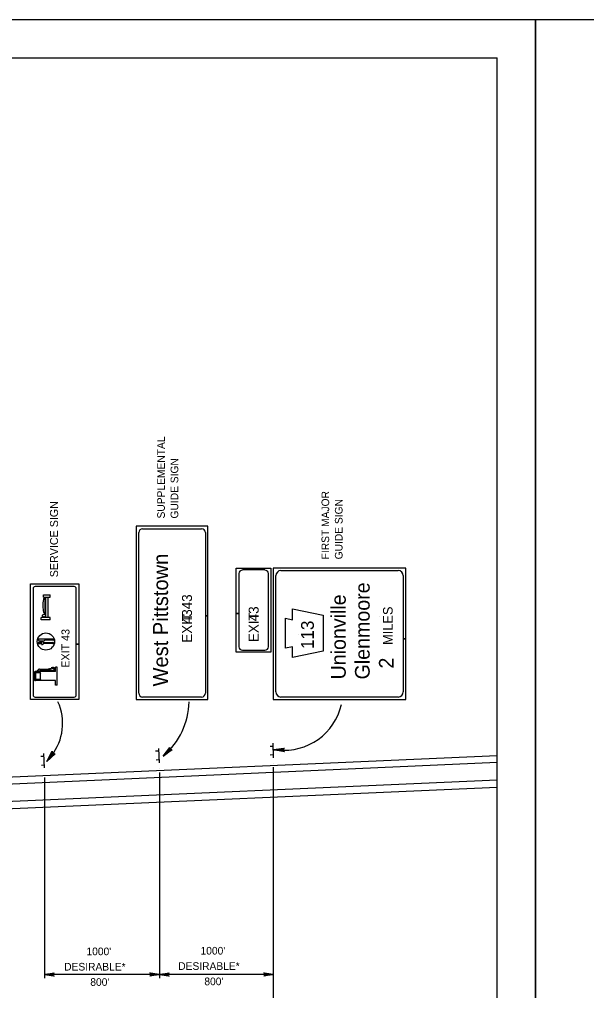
# Model space of a CAD drawing. Extents: x 644898 to 648326, y 298294 to 300670.
# Drawn here: x 646378.1 to 646600.3, y 300290.3 to 300670.5 of the extents above; entities that cross this region are included whole.
import ezdxf

# ---------------------------------------------------------------- set-up
doc = ezdxf.new("R2010")
doc.units = 0
for name, color, linetype in [('1', 7, 'Continuous'), ('2', 7, 'Continuous'), ('XCS-GRID-MIN', 7, 'Continuous')]:
    doc.layers.add(name, color=color, linetype=linetype)

msp = doc.modelspace()

# ---------------------------------------------------------------- linework, layer by layer
at = {"layer": '1'}
for p in [(645779.32, 300655.49), (646565.32, 300091.49)]:
    msp.add_line(p, (646565.32, 300655.49), dxfattribs=at)
at = {"layer": '2'}
for p, q in [((646451.95, 300472.12), (646423.82, 300472.12)), ((646423.82, 300472.12), (646423.82, 300404.24)), ((646424.82, 300406.74), (646424.82, 300469.62)), ((646426.32, 300471.12), (646426.32, 300471.12)), ((646426.32, 300471.12), (646449.45, 300471.12)), ((646449.45, 300471.12), (646449.45, 300471.12)), ((646450.95, 300469.62), (646450.95, 300436.98)), ((646451.95, 300436.98), (646451.95, 300472.12)), ((646463.07, 300437.92), (646463.07, 300455.74)), ((646463.07, 300455.74), (646476.57, 300455.74)), ((646464.07, 300453.62), (646464.07, 300437.92)), ((646474.2, 300454.99), (646465.45, 300454.99)), ((646475.7, 300424.74), (646475.7, 300453.62)), ((646476.57, 300455.74), (646476.57, 300422.74)), ((646529.45, 300455.74), (646477.57, 300455.74)), ((646477.57, 300455.74), (646477.57, 300404.24)), ((646480.57, 300454.74), (646526.45, 300454.74)), ((646529.45, 300428), (646529.45, 300455.74)), ((646478.57, 300407.24), (646478.57, 300452.74)), ((646528.45, 300452.74), (646528.45, 300428)), ((646382.45, 300404.24), (646382.45, 300449.49)), ((646382.45, 300449.49), (646401.32, 300449.49)), ((646383.45, 300447.74), (646383.45, 300405.99)), ((646399.57, 300448.49), (646384.2, 300448.49)), ((646400.32, 300425.97), (646400.32, 300447.74)), ((646401.32, 300449.49), (646401.32, 300425.97)), ((646387.57, 300444.37), (646387.57, 300445.24)), ((646387.57, 300445.24), (646390.07, 300445.24)), ((646387.57, 300444.37), (646390.07, 300444.37)), ((646388.2, 300437.87), (646388.2, 300444.12)), ((646388.45, 300436.37), (646388.45, 300444.37)), ((646389.32, 300436.37), (646389.32, 300444.37)), ((646390.07, 300444.37), (646390.07, 300445.24)), ((646388.45, 300440.37), (646388.45, 300440.37)), ((646469.82, 300439.24), (646469.82, 300439.24)), ((646485.07, 300435.49), (646485.07, 300439.74)), ((646485.07, 300439.74), (646497.07, 300437.24)), ((646390.07, 300436.37), (646386.57, 300436.37)), ((646386.57, 300435.49), (646386.57, 300436.37)), ((646390.07, 300435.49), (646386.57, 300435.49)), ((646390.07, 300435.49), (646390.07, 300436.37)), ((646450.95, 300436.98), (646451.95, 300436.98)), ((646451.95, 300436.98), (646450.95, 300436.98)), ((646450.95, 300436.98), (646450.95, 300406.74)), ((646451.95, 300404.24), (646451.95, 300436.98)), ((646463.07, 300437.92), (646464.07, 300437.92)), ((646464.07, 300437.92), (646463.07, 300437.92)), ((646463.07, 300422.74), (646463.07, 300437.92)), ((646464.07, 300437.92), (646464.07, 300424.74)), ((646482.32, 300430.24), (646482.32, 300436.12)), ((646482.32, 300436.12), (646485.07, 300435.49)), ((646497.07, 300437.24), (646497.07, 300430.12)), ((646519.32, 300436.62), (646519.32, 300436.62)), ((646385.45, 300426.62), (646386.57, 300426.87)), ((646391.32, 300427.87), (646385.57, 300427.87)), ((646385.57, 300427.87), (646385.57, 300427.62)), ((646387.57, 300427.12), (646385.95, 300427.12)), ((646391.32, 300427.49), (646388.2, 300427.49)), ((646482.32, 300424.37), (646482.32, 300430.24)), ((646487.45, 300429.74), (646487.45, 300429.74)), ((646487.45, 300429.74), (646487.45, 300429.74)), ((646487.45, 300429.74), (646487.45, 300429.74)), ((646487.45, 300429.74), (646487.45, 300429.74)), ((646497.07, 300430.37), (646497.07, 300423.24)), ((646528.45, 300428), (646529.45, 300428)), ((646529.45, 300428), (646528.45, 300428)), ((646528.45, 300428), (646528.45, 300407.24)), ((646529.45, 300404.24), (646529.45, 300428)), ((646386.82, 300426.49), (646385.45, 300426.62)), ((646386.82, 300426.37), (646385.45, 300426.49)), ((646385.45, 300426.49), (646386.82, 300426.49)), ((646385.45, 300426.24), (646386.45, 300426.37)), ((646386.95, 300426.12), (646385.45, 300426.24)), ((646385.45, 300425.99), (646386.95, 300426.12)), ((646386.82, 300425.87), (646385.45, 300425.99)), ((646386.45, 300426.37), (646386.82, 300426.37)), ((646391.32, 300426.49), (646387.7, 300426.49)), ((646391.32, 300426.12), (646387.7, 300426.12)), ((646400.32, 300425.97), (646401.32, 300425.97)), ((646401.32, 300425.97), (646400.32, 300425.97)), ((646400.32, 300405.99), (646400.32, 300425.97)), ((646401.32, 300425.97), (646401.32, 300404.24)), ((646465.45, 300423.62), (646474.2, 300423.62)), ((646485.07, 300424.87), (646482.32, 300424.37)), ((646485.07, 300420.74), (646485.07, 300424.87)), ((646497.07, 300423.24), (646485.07, 300420.74)), ((646476.57, 300422.74), (646463.07, 300422.74)), ((646384.82, 300415.24), (646385.45, 300415.87)), ((646385.45, 300415.37), (646385.32, 300415.24)), ((646386.2, 300415.37), (646385.45, 300415.37)), ((646385.95, 300416.12), (646389.2, 300416.12)), ((646386.2, 300415.87), (646389.2, 300415.87)), ((646386.2, 300415.87), (646386.2, 300415.37)), ((646387.32, 300415.24), (646387.32, 300415.37)), ((646387.57, 300415.62), (646390.82, 300415.62)), ((646387.7, 300415.37), (646391.32, 300415.37)), ((646389.82, 300416.37), (646390.57, 300416.49)), ((646389.95, 300415.99), (646390.7, 300416.24)), ((646392.2, 300415.24), (646392.2, 300416.87)), ((646392.82, 300416.87), (646392.2, 300416.87)), ((646392.82, 300409.87), (646392.82, 300416.87)), ((646383.95, 300412.12), (646383.95, 300414.74)), ((646392.2, 300415.24), (646384.32, 300415.24)), ((646392.2, 300411.74), (646384.32, 300411.74)), ((646386.2, 300414.74), (646384.45, 300414.74)), ((646384.45, 300412.37), (646384.45, 300414.62)), ((646386.2, 300412.12), (646384.45, 300412.12)), ((646386.32, 300412.37), (646386.32, 300414.49)), ((646387.57, 300415.24), (646387.57, 300415.24)), ((646392.2, 300409.87), (646392.2, 300411.74)), ((646392.82, 300409.87), (646392.2, 300409.87)), ((646401.32, 300404.24), (646382.45, 300404.24)), ((646384.2, 300405.24), (646399.57, 300405.24)), ((646423.82, 300404.24), (646451.95, 300404.24)), ((646426.32, 300405.24), (646426.32, 300405.24)), ((646449.45, 300405.24), (646426.32, 300405.24)), ((646449.45, 300405.24), (646449.45, 300405.24)), ((646477.57, 300404.24), (646529.45, 300404.24)), ((646526.45, 300405.24), (646480.57, 300405.24)), ((646432.57, 300385.12), (646432.82, 300379.49)), ((646477.45, 300385.87), (646476.32, 300385.87)), ((646477.32, 300387.12), (646477.57, 300381.49)), ((646204.57, 300366.49), (646565.32, 300382.33)), ((646387.57, 300381.99), (646386.45, 300381.99)), ((646387.57, 300383.12), (646387.82, 300377.49)), ((646432.57, 300383.99), (646431.45, 300383.99)), ((646477.57, 300382.62), (646476.32, 300382.49)), ((646074.45, 300357.99), (646565.32, 300379.71)), ((646387.82, 300378.62), (646386.7, 300378.49)), ((646432.7, 300380.62), (646431.7, 300380.49)), ((646477.57, 300379.24), (646477.57, 300379.24)), ((646477.57, 300377.74), (646477.57, 300259.62)), ((646387.95, 300373.74), (646387.95, 300295.12)), ((646432.95, 300377.24), (646432.95, 300377.24)), ((646432.95, 300375.74), (646432.95, 300295.12)), ((646075.95, 300351.37), (646565.32, 300372.83)), ((646201.32, 300353.99), (646565.32, 300369.96)), ((646432.95, 300296.62), (646387.95, 300296.62)), ((646477.57, 300296.62), (646432.95, 300296.62))]:
    msp.add_line(p, q, dxfattribs=at)
for points in [[(646437.7, 300384.57), (646437.32, 300384.67), (646434.37, 300382.08), (646437.7, 300384.57), (646437.95, 300384.59), (646434.37, 300382.08), (646437.04, 300385.02), (646437.03, 300385.27), (646434.37, 300382.08), (646437.01, 300385.52), (646437.03, 300385.27)], [(646481.57, 300384.12), (646481.57, 300384.37), (646477.7, 300384.62), (646481.57, 300384.12), (646481.95, 300383.74), (646477.7, 300384.62), (646481.57, 300384.74), (646481.7, 300385.12), (646477.7, 300384.62), (646481.95, 300385.12), (646481.7, 300385.12)], [(646391.79, 300382.96), (646391.53, 300383.05), (646388.83, 300380.01), (646391.79, 300382.96), (646392.04, 300382.98), (646388.83, 300380.01), (646391.12, 300383.39), (646390.97, 300383.62), (646388.83, 300380.01), (646390.93, 300384), (646390.97, 300383.62)], [(646391.45, 300296.12), (646391.32, 300296.37), (646387.95, 300296.62), (646391.45, 300296.12), (646391.7, 300295.99), (646387.95, 300296.62), (646391.32, 300296.74), (646391.45, 300296.99), (646387.95, 300296.62), (646391.7, 300297.24), (646391.45, 300296.99)], [(646429.45, 300297.12), (646429.57, 300296.87), (646432.95, 300296.62), (646429.45, 300297.12), (646429.2, 300297.24), (646432.95, 300296.62), (646429.57, 300296.49), (646429.45, 300296.24), (646432.95, 300296.62), (646429.2, 300295.99), (646429.45, 300296.24)], [(646436.45, 300296.12), (646436.32, 300296.37), (646432.95, 300296.62), (646436.45, 300296.12), (646436.7, 300295.99), (646432.95, 300296.62), (646436.32, 300296.74), (646436.45, 300296.99), (646432.95, 300296.62), (646436.7, 300297.24), (646436.45, 300296.99)], [(646474.07, 300297.12), (646474.2, 300296.87), (646477.57, 300296.62), (646474.07, 300297.12), (646473.82, 300297.24), (646477.57, 300296.62), (646474.2, 300296.49), (646474.07, 300296.24), (646477.57, 300296.62), (646473.82, 300295.99), (646474.07, 300296.24)]]:
    msp.add_lwpolyline(points, dxfattribs=at)
for centre, radius in [((646387.72, 300437.12), 0.598), ((646388.45, 300426.96), 3.38)]:
    msp.add_circle(centre, radius, dxfattribs=at)
for centre, radius, start, end in [((646426.32, 300469.62), 1.5, 90, 180), ((646449.45, 300469.62), 1.5, 0, 90), ((646480.57, 300452.74), 2, 90, 180), ((646526.45, 300452.74), 2, 0, 90), ((646384.2, 300447.74), 0.75, 90, 180), ((646399.57, 300447.74), 0.75, 0, 90), ((646402.82, 300441.11), 15.54, 171.2295, 181.1783), ((646388.2, 300443.39), 0.74, 84.1655, 172.9293), ((646406.03, 300441.07), 18.75, 180.8408, 188.1781), ((646388.27, 300438.74), 0.868, 202.8419, 269.9082), ((646385.94, 300427.57), 0.422, 180, 270), ((646386.82, 300426.08), 0.83, 44.7019, 103.537), ((646387.43, 300427.83), 0.696, 281.1263, 314.137), ((646388.18, 300427.08), 0.369, 83.1408, 137.1102), ((646391.27, 300427.66), 0.218, 261.5053, 98.4947), ((646386.87, 300426.51), 0.724, 261.5401, 313.94), ((646387.75, 300425.67), 0.494, 95.8318, 139.6318), ((646387.7, 300426.96), 0.42, 224.9301, 269.654), ((646391.27, 300426.35), 0.195, 258.6255, 101.3745), ((646386.03, 300415.34), 0.826, 95.5404, 137.2088), ((646387.63, 300415.38), 0.265, 89.4256, 167.8581), ((646387.72, 300415.3), 0.0642, 79.1965, 181.8396), ((646388.9, 300418.62), 2.48, 276.6108, 292.2765), ((646388.9, 300418.62), 2.79, 276.6108, 292.2765), ((646391.54, 300414.58), 2.24, 92.3973, 115.3499), ((646391.32, 300415.11), 1.32, 82.2446, 117.6633), ((646390.89, 300416.92), 1.27, 271.1053, 299.4807), ((646391.3, 300416.15), 0.794, 269.2148, 356.6422), ((646391.39, 300416.12), 0.7, 359.2139, 85.3444), ((646391.4, 300416.11), 0.318, 289.9687, 73.0966), ((646384.34, 300414.81), 0.405, 97.9024, 178.9277), ((646384.28, 300412.06), 0.346, 171.6254, 276.5874), ((646384.61, 300414.55), 0.228, 107.0861, 183.3769), ((646384.59, 300412.36), 0.207, 168.286, 258.2569), ((646386.1, 300414.46), 0.327, 355.7148, 73.5391), ((646386.16, 300412.42), 0.262, 276.241, 356.6554), ((646384.2, 300405.99), 0.75, 180, 270), ((646399.57, 300405.99), 0.75, 270, 0), ((646426.32, 300406.74), 1.5, 180, 270), ((646449.45, 300406.74), 1.5, 270, 360), ((646480.57, 300407.24), 2, 180, 270), ((646526.45, 300407.24), 2, 270, 360), ((646374.62, 300394.88), 20.4, 321.9627, 24.5125), ((646416.27, 300403.84), 28.27, 310.2091, 358.9986), ((646481.86, 300407.36), 22.95, 263.5843, 347.307)]:
    msp.add_arc(centre, radius, start, end, dxfattribs=at)
for centre, major_axis, start_param, end_param in [((646465.46, 300453.64), (-1.41, 0), 4.712389, 6.283185), ((646474.26, 300453.64), (-1.41, 0), 3.141593, 4.712389), ((646465.46, 300424.83), (1.41, 0), 3.141593, 4.712389), ((646474.26, 300424.83), (1.41, 0), 4.712389, 6.283185)]:
    msp.add_ellipse(centre, major_axis=major_axis, ratio=0.910229, start_param=start_param, end_param=end_param, dxfattribs=at)
at = {"layer": 'XCS-GRID-MIN'}
for points in [[(645739.32, 300670.49), (646580.32, 300670.49), (646580.32, 300076.49), (645739.32, 300076.49)], [(646580.32, 300670.49), (647421.32, 300670.49), (647421.32, 300076.49), (646580.32, 300076.49)]]:
    msp.add_lwpolyline(points, close=True, dxfattribs=at)

# ---------------------------------------------------------------- texts
at = {"layer": '2'}
for s, height, p in [('SUPPLEMENTAL', 3, (646435.07, 300475.12)), ('GUIDE SIGN', 3, (646440.32, 300475.12)), ('FIRST MAJOR', 3, (646499.45, 300459.12)), ('SERVICE SIGN', 3.1342, (646393.2, 300452.12)), ('GUIDE SIGN', 3, (646504.7, 300459.12)), ('West Pittstown', 5.8747, (646436.32, 300409.37)), ('Glenmoore', 5.743, (646515.32, 300412.12)), ('EXIT 43', 3.918, (646445.7, 300426.49)), ('Unionville', 5.743, (646505.95, 300412.12)), ('     43', 3.918, (646445.7, 300426.49)), ('     43', 3.918, (646471.82, 300427.62)), ('EXIT   ', 3.918, (646471.82, 300426.74)), ('MILES', 3.75, (646524.32, 300425.62)), ('113', 5, (646493.45, 300423.99)), ('EXIT 43', 3.134, (646397.7, 300416.72)), ('  2 ', 5.743, (646524.7, 300412.12))]:
    msp.add_text(s, height=height, rotation=90, dxfattribs=at).set_placement(p)
for s, p in [("1000'", (646404.35, 300304.15)), ("1000'", (646449.04, 300304.41)), (' DESIRABLE*', (646439.2, 300298.41)), (' DESIRABLE*', (646394.5, 300298.15)), ("800'", (646405.85, 300292.15)), ("800'", (646450.54, 300292.41))]:
    msp.add_text(s, height=3, dxfattribs=at).set_placement(p)

doc.saveas('drawing.dxf')
